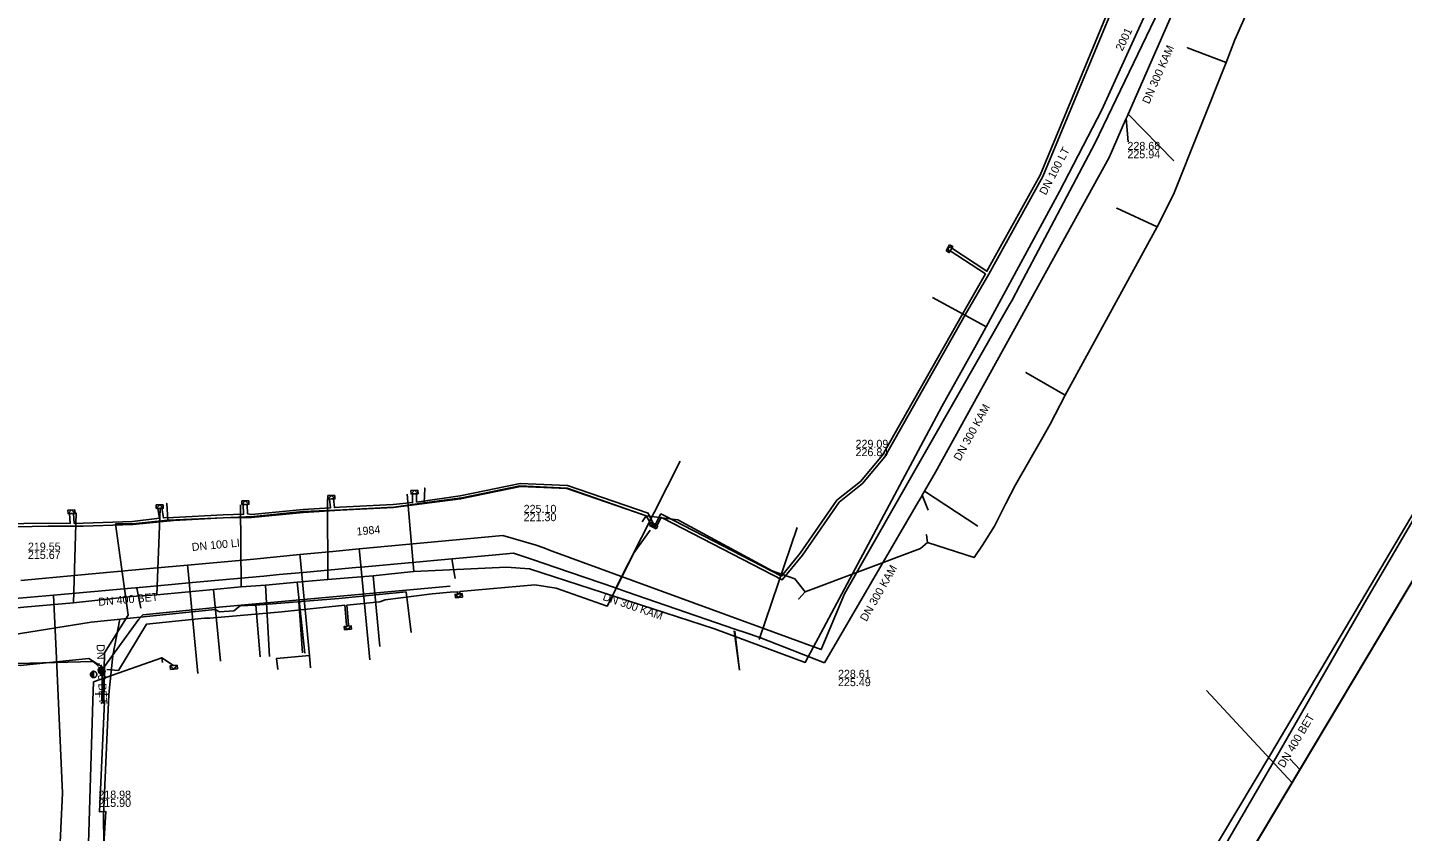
# Model space of a CAD drawing. Extents: x -596024 to -594475, y -1163820 to -1161957.
# Drawn here: x -595805.3 to -595667.9, y -1163008.8 to -1162928.4 of the extents above; entities that cross this region are included whole.
import ezdxf

# ---------------------------------------------------------------- set-up
doc = ezdxf.new("R2010")
doc.units = 0
for name, color, linetype in [('13', 7, 'Continuous'), ('31', 7, 'Continuous'), ('Level 1', 7, 'Continuous'), ('Vrstva 1', 7, 'Continuous'), ('Vrstva 12', 7, 'Continuous'), ('Vrstva 13', 7, 'Continuous'), ('Vrstva 15', 7, 'Continuous'), ('Vrstva 16', 7, 'Continuous'), ('Vrstva 25', 7, 'Continuous'), ('Vrstva 28', 7, 'Continuous'), ('Vrstva 4', 7, 'Continuous'), ('Vrstva 42', 7, 'Continuous'), ('Vrstva 43', 7, 'Continuous'), ('Vrstva 51', 7, 'Continuous'), ('Vrstva 55', 7, 'Continuous'), ('Vrstva 9', 7, 'Continuous')]:
    doc.layers.add(name, color=color, linetype=linetype)

# ---------------------------------------------------------------- blocks, each defined once
blk = doc.blocks.new('NN630')
at = {"layer": '31'}
for points in [[(-0.003, -0.7), (-0.703, 0)], [(-0.703, -0.7), (-0.703, 0), (0.697, 0), (0.697, -0.7)], [(-0.003, -0.7), (0.697, 0)], [(-0.703, -0.7), (0.697, -0.7)]]:
    blk.add_lwpolyline(points, dxfattribs=at)
blk = doc.blocks.new('NN510')
at = {"layer": '13'}
blk.add_lwpolyline([(0.001, 0.002), (0.001, 0.939)], dxfattribs=at)
blk = doc.blocks.new('NN440')
at = {"layer": '13'}
for points in [[(-0.631, 0), (0.629, 0)], [(0.631, -0.004), (0.627, 0.062), (0.617, 0.127), (0.6, 0.191), (0.577, 0.252), (0.547, 0.311), (0.511, 0.366), (0.469, 0.417), (0.423, 0.464), (0.371, 0.505), (0.316, 0.542), (0.257, 0.571), (0.196, 0.595), (0.132, 0.612), (0.067, 0.622), (0.001, 0.626), (-0.065, 0.622), (-0.13, 0.612), (-0.194, 0.595), (-0.255, 0.571), (-0.314, 0.542), (-0.369, 0.505), (-0.42, 0.464), (-0.467, 0.417), (-0.509, 0.366), (-0.544, 0.311), (-0.574, 0.252), (-0.598, 0.191), (-0.615, 0.127), (-0.626, 0.062), (-0.629, -0.004), (-0.626, -0.07), (-0.615, -0.135), (-0.598, -0.199), (-0.574, -0.26), (-0.544, -0.319), (-0.509, -0.374), (-0.467, -0.426), (-0.42, -0.472), (-0.369, -0.514), (-0.314, -0.55), (-0.255, -0.58), (-0.194, -0.603), (-0.13, -0.62), (-0.065, -0.631), (0.001, -0.634), (0.067, -0.631), (0.132, -0.62), (0.196, -0.603), (0.257, -0.58), (0.316, -0.55), (0.371, -0.514), (0.423, -0.472), (0.469, -0.426), (0.511, -0.374), (0.547, -0.319), (0.577, -0.26), (0.6, -0.199), (0.617, -0.135), (0.627, -0.07), (0.631, -0.004)], [(-0.601, -0.177), (0.57, -0.177)], [(-0.513, -0.325), (0.501, -0.325)], [(-0.375, -0.473), (0.353, -0.473)]]:
    blk.add_lwpolyline(points, dxfattribs=at)
blk = doc.blocks.new('NN620')
at = {"layer": 'Vrstva 28'}
for points in [[(0.752, 0.004), (-0.748, 0.004)], [(-0.748, 0.004), (-0.748, -0.746)], [(0.752, -0.746), (0.752, 0.004)], [(-0.748, -0.746), (0.752, -0.746)], [(0.368, -0.18), (-0.376, -0.18)], [(-0.376, -0.18), (-0.376, -0.558)], [(-0.376, -0.558), (0.368, -0.558)], [(0.321, -0.227), (-0.329, -0.227)], [(-0.329, -0.227), (-0.329, -0.51)], [(-0.329, -0.51), (0.321, -0.51)], [(0.274, -0.274), (-0.281, -0.274)], [(-0.281, -0.274), (-0.281, -0.463)], [(-0.281, -0.463), (0.274, -0.463)], [(0.227, -0.321), (-0.234, -0.321)], [(-0.234, -0.321), (-0.234, -0.416)], [(-0.234, -0.416), (0.227, -0.416)], [(-0.193, -0.369), (0.185, -0.369)], [(0.227, -0.416), (0.227, -0.321)], [(0.274, -0.463), (0.274, -0.274)], [(0.321, -0.51), (0.321, -0.227)], [(0.368, -0.558), (0.368, -0.18)]]:
    blk.add_lwpolyline(points, dxfattribs=at)

msp = doc.modelspace()

# ---------------------------------------------------------------- linework, layer by layer
at = {"layer": 'Level 1'}
for points in [[(-595609.54, -1162875.48), (-595633.36, -1162922.71), (-595657.34, -1162967.78), (-595683.27, -1163011.26), (-595711.29, -1163052.41), (-595741.62, -1163091.74), (-595776.38, -1163127.71), (-595816.28, -1163159.56), (-595860.78, -1163185.25), (-595904.58, -1163202.66), (-595939.49, -1163211.28), (-595963.53, -1163187.96), (-595972.46, -1163189.04), (-595993.41, -1163187.54), (-595999.33, -1163186.65), (-596024.42, -1163184.939)], [(-595695.46, -1162937.49), (-595695.26, -1162939.84)], [(-595695.28, -1162937.07), (-595690.7, -1162941.73)], [(-595740.04, -1162971.74), (-595746.52, -1162984.5)], [(-595715.28, -1162976.66), (-595715.86, -1162975.16)], [(-595710.31, -1162978.24), (-595715.62, -1162974.74)], [(-595732.15, -1162989.59), (-595728.36, -1162978.39)], [(-595762.55, -1162983.48), (-595762.87, -1162981.52)], [(-595793.95, -1162986.46), (-595794.35, -1162984.45)], [(-595734.12, -1162992.64), (-595734.66, -1162988.7)], [(-595734.12, -1162992.63), (-595734.6, -1162988.73)], [(-595687.46, -1162994.67), (-595678.89, -1163003.92)], [(-595679.1, -1163001.49), (-595678.1, -1163002.6)]]:
    msp.add_lwpolyline(points, dxfattribs=at)
at = {"layer": 'Vrstva 1'}
msp.add_line((-595657.36, -1162967.74), (-595683.3, -1163011.28), dxfattribs=at)
at = {"layer": 'Vrstva 13'}
for points in [[(-595691.75, -1162925.735), (-595698.61, -1162940), (-595706.11, -1162954.191), (-595706.88, -1162955.65), (-595707.17, -1162956.154), (-595723.63, -1162985.02), (-595725.95, -1162990.59), (-595752.837, -1162980.749), (-595753.78, -1162980.39), (-595754.435, -1162980.153)], [(-595805.955, -1162983.689), (-595800.236, -1162983.145), (-595792.699, -1162982.434), (-595789.273, -1162982.129), (-595782.644, -1162981.532), (-595778.049, -1162981.078), (-595774.777, -1162980.772), (-595772.121, -1162980.523), (-595765.671, -1162979.918), (-595757.763, -1162979.178), (-595754.435, -1162980.153)], [(-595772.121, -1162980.523), (-595772.098, -1162980.777), (-595771.082, -1162991.608)], [(-595789.273, -1162982.129), (-595789.246, -1162982.42), (-595788.256, -1162992.991)], [(-595778.049, -1162981.078), (-595778.023, -1162981.358), (-595777.104, -1162991.16), (-595776.988, -1162992.399)], [(-595777.104, -1162991.16), (-595780.382, -1162991.467), (-595780.253, -1162992.562)]]:
    msp.add_lwpolyline(points, dxfattribs=at)
at = {"layer": 'Vrstva 16'}
for points in [[(-595692.22, -1162924.07), (-595697.92, -1162936.64), (-595702.15, -1162944.8), (-595709.46, -1162958.31), (-595710.43, -1162960.09), (-595713.89, -1162966.27), (-595727.55, -1162991.87), (-595736.62, -1162988.52), (-595755.1, -1162982.52), (-595757.41, -1162982.34), (-595766.66, -1162982.77), (-595768.91, -1162983.01)], [(-595709.46, -1162958.31), (-595709.64, -1162958.22), (-595711.39, -1162957.26), (-595714.83, -1162955.4)], [(-595766.66, -1162982.77), (-595767.35, -1162975.04)], [(-595792.36, -1162985.1), (-595792.03, -1162976.51)], [(-595783.91, -1162984.32), (-595783.98, -1162976.13)], [(-595775.26, -1162983.57), (-595775.29, -1162975.54)], [(-595800.67, -1162985.9), (-595800.4, -1162976.92)], [(-595768.91, -1162983.01), (-595770.73, -1162983.2), (-595775.26, -1162983.57), (-595778.34, -1162983.85), (-595781.48, -1162984.13), (-595783.91, -1162984.32), (-595786.7, -1162984.59), (-595792.36, -1162985.1), (-595794.87, -1162985.27), (-595800.67, -1162985.9), (-595805.65, -1162986.36), (-595815.38, -1162987.29), (-595822.51, -1162987.94), (-595823.73, -1162988.13), (-595827.32, -1162988.38), (-595838.51, -1162989.4), (-595855.98, -1162991.08), (-595856.38, -1162991.12), (-595864.37, -1162991.89), (-595886.83, -1162993.96), (-595891.02, -1162994.31), (-595892.36, -1162994.43), (-595895.41, -1162994.94), (-595900.64, -1162995.37)], [(-595770.73, -1162983.2), (-595770.08, -1162990.27)], [(-595786.7, -1162984.59), (-595785.99, -1162991.74)], [(-595781.48, -1162984.13), (-595781.1, -1162991.27)], [(-595778.34, -1162983.85), (-595777.57, -1162990.93)]]:
    msp.add_lwpolyline(points, dxfattribs=at)
at = {"layer": 'Vrstva 25'}
for p, q in [((-595767.447, -1162984.818), (-595774.156, -1162985.488)), ((-595766.928, -1162988.866), (-595767.447, -1162984.818)), ((-595784.027, -1162986.2), (-595784.668, -1162986.72)), ((-595782.453, -1162986.153), (-595784.027, -1162986.2)), ((-595774.156, -1162985.488), (-595782.453, -1162986.153)), ((-595782.453, -1162986.153), (-595782.018, -1162991.314)), ((-595778.15, -1162985.808), (-595777.785, -1162990.913)), ((-595786.527, -1162986.568), (-595798.933, -1162987.835)), ((-595796.064, -1162987.542), (-595796.749, -1162991.185)), ((-595786.081, -1162986.809), (-595786.527, -1162986.568)), ((-595784.668, -1162986.72), (-595786.081, -1162986.809)), ((-595798.933, -1162987.835), (-595806.804, -1162989.096)), ((-595796.749, -1162991.185), (-595797.142, -1162995.061)), ((-595797.142, -1162995.061), (-595798.507, -1162995.013)), ((-595797.142, -1162995.061), (-595797.681, -1163007.177)), ((-595797.681, -1163007.177), (-595797.654, -1163009.979))]:
    msp.add_line(p, q, dxfattribs=at)
at = {"layer": 'Vrstva 42'}
for points in [[(-595742.344, -1162978.159), (-595741.965, -1162977.366), (-595741.785, -1162977.458), (-595729.841, -1162983.609), (-595727.83, -1162981.14), (-595724.169, -1162975.854), (-595721.815, -1162973.988), (-595719.596, -1162971.316), (-595711.55, -1162957.124), (-595709.209, -1162953.054), (-595703.795, -1162943.295), (-595696.888, -1162926.646), (-595697.024, -1162924.269), (-595698.97, -1162923.163), (-595698.88, -1162923.027), (-595698.784, -1162922.902), (-595696.975, -1162923.95), (-595694.006, -1162919.494), (-595692.928, -1162917.913), (-595688.388, -1162907.559), (-595687.875, -1162905.507), (-595690.849, -1162895.069), (-595691.201, -1162894.28), (-595691.24, -1162894.08)], [(-595742.522, -1162978.05), (-595741.969, -1162977.025), (-595741.647, -1162977.192), (-595729.919, -1162983.231), (-595728.07, -1162980.96), (-595724.391, -1162975.646), (-595722.025, -1162973.772), (-595719.844, -1162971.144), (-595711.81, -1162956.976), (-595709.541, -1162953.027), (-595713.068, -1162950.718), (-595712.979, -1162950.591), (-595712.89, -1162950.448), (-595709.393, -1162952.766), (-595704.065, -1162943.165), (-595697.192, -1162926.594)], [(-595743.144, -1162977.704), (-595743.442, -1162977.198), (-595751.376, -1162974.488), (-595756.016, -1162974.291), (-595761.991, -1162975.516), (-595768.703, -1162976.379), (-595774.043, -1162976.66), (-595777.717, -1162976.879), (-595782.883, -1162977.38), (-595785.729, -1162977.43), (-595790.668, -1162977.689), (-595794.751, -1162978.069), (-595799.709, -1162978.251), (-595803.228, -1162978.24), (-595809.609, -1162978.365)], [(-595742.786, -1162977.907), (-595743.24, -1162976.95), (-595751.32, -1162974.19), (-595756.04, -1162973.99), (-595762.04, -1162975.22), (-595766.39, -1162975.841), (-595766.4, -1162975.008), (-595766.6, -1162975.01), (-595766.8, -1162975.012), (-595766.79, -1162975.883), (-595768.73, -1162976.08), (-595774.06, -1162976.36), (-595774.6, -1162976.387), (-595774.701, -1162975.507), (-595774.9, -1162975.53), (-595775.099, -1162975.553), (-595775, -1162976.415), (-595777.74, -1162976.58), (-595782.9, -1162977.08), (-595783.29, -1162977.025), (-595783.31, -1162976.066), (-595783.51, -1162976.07), (-595783.71, -1162976.074), (-595783.69, -1162977.049), (-595785.74, -1162977.13), (-595790.69, -1162977.39), (-595791.699, -1162977.421), (-595791.863, -1162976.427), (-595792.06, -1162976.46), (-595792.257, -1162976.493), (-595792.1, -1162977.442), (-595794.77, -1162977.77), (-595799.714, -1162977.951), (-595800.61, -1162977.968), (-595800.68, -1162976.966), (-595800.88, -1162976.98), (-595801.08, -1162976.994), (-595801.011, -1162977.977), (-595803.23, -1162977.94), (-595808.11, -1162978.03)], [(-595797.366, -1162992.591), (-595796.19, -1162992.69), (-595793.39, -1162988.06), (-595787.58, -1162987.43), (-595787.05, -1162987.45), (-595779.86, -1162986.8), (-595773.56, -1162986.15), (-595773.393, -1162988.102), (-595773.28, -1162988.24), (-595773.191, -1162988.102), (-595773.36, -1162986.131), (-595770.07, -1162985.82), (-595769.52, -1162985.6), (-595764.84, -1162985.02), (-595763.03, -1162984.85), (-595762.261, -1162984.797), (-595762.292, -1162984.971), (-595762.2, -1162985.03), (-595762.083, -1162984.941), (-595762.057, -1162984.781), (-595754.58, -1162984.1), (-595752.45, -1162984.45), (-595747.35, -1162986.26), (-595744.64, -1162980.89), (-595743.04, -1162978.635)], [(-595807.57, -1162992.01), (-595798.72, -1162991.77), (-595798.261, -1162992.136)]]:
    msp.add_lwpolyline(points, dxfattribs=at)
at = {"layer": 'Vrstva 51'}
for points in [[(-595798.693, -1162993.822), (-595791.859, -1162991.405), (-595790.683, -1162992.186)], [(-595798.693, -1162993.822), (-595798.752, -1162995.701), (-595799.6, -1163023.09), (-595799.91, -1163059.77)]]:
    msp.add_lwpolyline(points, dxfattribs=at)
at = {"layer": 'Vrstva 55'}
for points in [[(-595861.545, -1163184.149), (-595840.235, -1163173.489), (-595821.055, -1163161.559), (-595807.835, -1163152.609), (-595783.535, -1163132.569), (-595767.875, -1163118.239), (-595756.215, -1163105.649), (-595737.945, -1163084.859), (-595715.895, -1163056.189), (-595701.725, -1163036.029), (-595690.385, -1163018.389), (-595680.305, -1163001.079), (-595671.485, -1162985.639), (-595658.565, -1162963.599), (-595646.285, -1162940.289), (-595632.685, -1162914.289), (-595612.515, -1162873.319), (-595603.855, -1162853.619), (-595604.51, -1162853.03)], [(-595904.003, -1163200.83), (-595885.89, -1163194.12), (-595862.2, -1163183.56), (-595840.89, -1163172.9), (-595821.71, -1163160.97), (-595808.49, -1163152.02), (-595784.19, -1163131.98), (-595768.53, -1163117.65), (-595756.87, -1163105.06), (-595738.6, -1163084.27), (-595716.55, -1163055.6), (-595702.38, -1163035.44), (-595691.04, -1163017.8), (-595681.06, -1163001.07), (-595661.01, -1162967.24), (-595642.49, -1162932.63), (-595625.54, -1162899.15), (-595608.632, -1162864.051)], [(-595743.84, -1162977.81), (-595743.46, -1162977.21), (-595740.29, -1162977.62), (-595730.87, -1162982.7), (-595728.58, -1162983.51), (-595727.55, -1162984.82), (-595728.2, -1162985.52), (-595727.55, -1162984.82), (-595716.03, -1162980.47), (-595715.32, -1162979.87), (-595715.43, -1162979.11), (-595715.32, -1162979.87), (-595710.65, -1162981.39), (-595709.82, -1162980.14), (-595708.62, -1162978.26), (-595707.5, -1162975.98), (-595706.53, -1162974.11), (-595703.94, -1162969.59), (-595703.07, -1162968.04), (-595701.58, -1162965.15), (-595705.49, -1162962.87), (-595701.58, -1162965.15), (-595692.39, -1162948.31), (-595696.41, -1162946.46), (-595692.39, -1162948.31), (-595690.75, -1162945.1), (-595685.49, -1162931.9), (-595689.35, -1162930.43), (-595685.49, -1162931.9), (-595684.6, -1162929.63), (-595678.1, -1162914.84)], [(-595797.58, -1162995.79), (-595797.67, -1162995.95), (-595797.57, -1162990.9), (-595795.23, -1162987.15), (-595796.48, -1162978.03), (-595794.8, -1162978.03), (-595791.27, -1162977.65), (-595791.37, -1162975.97), (-595791.27, -1162977.65), (-595785.72, -1162977.43), (-595782.68, -1162977.27), (-595777.74, -1162976.78), (-595773.77, -1162976.62), (-595768.67, -1162976.35), (-595765.63, -1162975.91), (-595765.57, -1162974.44), (-595765.63, -1162975.91), (-595761.88, -1162975.42), (-595756.07, -1162974.23), (-595751.34, -1162974.44), (-595743.46, -1162977.21), (-595743.84, -1162977.81)], [(-595797.935, -1162995.99), (-595797.641, -1162995.725), (-595797.577, -1162992.268), (-595794.16, -1162987.53), (-595793.75, -1162987.1), (-595786.13, -1162986.33), (-595763.05, -1162984.25)], [(-595939.819, -1163011.071), (-595940.502, -1163004.494), (-595940.962, -1163003.452), (-595941.718, -1163002.328), (-595941.65, -1163002.05), (-595933.08, -1163001.23), (-595932.07, -1163000.53), (-595930.62, -1163000.08), (-595928.42, -1162999.84), (-595907.67, -1162997.81), (-595879.11, -1162994.94), (-595854.57, -1162992.8), (-595830.89, -1162990.61), (-595812.28, -1162988.92), (-595811.32, -1162989.67), (-595808.88, -1162991.91), (-595806.03, -1162992.18), (-595799.16, -1162991.49), (-595797.779, -1162992.349), (-595797.839, -1162995.635), (-595797.925, -1162995.712)], [(-595797.58, -1162995.79), (-595798.1, -1163006.79), (-595797.46, -1163006.77), (-595798.03, -1163016.07)]]:
    msp.add_lwpolyline(points, dxfattribs=at)
at = {"layer": 'Vrstva 9'}
for points in [[(-595697.17, -1162941.38), (-595695.529, -1162937.64), (-595695.462, -1162937.488), (-595695.344, -1162937.219), (-595695.277, -1162937.067), (-595690.133, -1162925.349), (-595690.132, -1162925.347), (-595687.556, -1162919.478), (-595687.407, -1162919.138), (-595679.788, -1162901.783), (-595679.19, -1162900.42)], [(-595714.54, -1162972.85), (-595706.61, -1162958.483), (-595697.17, -1162941.38)], [(-595714.54, -1162972.85), (-595715.619, -1162974.741), (-595715.857, -1162975.158), (-595716.001, -1162975.405), (-595716.217, -1162975.776), (-595725.619, -1162991.918)], [(-595756.692, -1162980.948), (-595758.465, -1162981.11), (-595771.56, -1162982.307), (-595772.466, -1162982.39), (-595777.714, -1162982.87), (-595780.134, -1162983.091), (-595781.658, -1162983.23), (-595782.056, -1162983.267), (-595789.167, -1162983.917), (-595790.84, -1162984.07), (-595794.494, -1162984.404), (-595794.903, -1162984.441), (-595797.492, -1162984.678), (-595802.67, -1162985.151)], [(-595725.619, -1162991.918), (-595731.151, -1162989.754), (-595732.08, -1162989.39), (-595733.557, -1162988.881), (-595734.482, -1162988.563), (-595745.424, -1162984.797), (-595746.5, -1162984.427), (-595752.487, -1162982.367), (-595753.631, -1162981.973), (-595754.698, -1162981.606), (-595756.692, -1162980.948)], [(-595802.67, -1162985.151), (-595805.752, -1162985.399), (-595816.885, -1162986.296), (-595824.84, -1162986.937), (-595829.136, -1162987.283), (-595831.07, -1162987.439), (-595833.093, -1162987.602), (-595834.927, -1162987.75)], [(-595801.773, -1163004.934), (-595802.418, -1162990.709), (-595802.67, -1162985.151)], [(-595801.773, -1163004.934), (-595802.109, -1163011.966), (-595802.214, -1163014.162), (-595802.28, -1163015.552), (-595802.371, -1163017.451), (-595802.503, -1163020.231), (-595802.54, -1163021)]]:
    msp.add_lwpolyline(points, dxfattribs=at)

# ---------------------------------------------------------------- block references
at = {"layer": 'Vrstva 43'}
for name, p, xscale, yscale, rotation in [('NN630', (-595712.979, -1162950.591), 0.5, 0.5, -119), ('NN630', (-595774.9, -1162975.53), 0.5, 0.5, -179.00000000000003), ('NN630', (-595766.6, -1162975.01), 0.5, 0.5, -179.00000000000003), ('NN630', (-595800.88, -1162976.98), 0.5, 0.5, -179.00000000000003), ('NN630', (-595792.06, -1162976.46), 0.5, 0.5, -179.00000000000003), ('NN630', (-595783.51, -1162976.07), 0.5, 0.5, -179.00000000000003), ('NN620', (-595742.61, -1162978.02), 0.49999999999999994, 0.5000000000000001, -28.99999999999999), ('NN630', (-595762.199, -1162985.029), 0.5, 0.5000000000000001, 6), ('NN630', (-595773.28, -1162988.24), 0.5, 0.5000000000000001, 6), ('NN510', (-595791.859, -1162991.405), 0.5, 0.49999999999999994, -173.00000000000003), ('NN440', (-595798.671, -1162993.07), 0.5, 0.5, -90.00000000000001), ('NN620', (-595798.061, -1162992.884), 0.5, 0.5, 119.99999999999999), ('NN630', (-595790.683, -1162992.187), 0.5, 0.5000000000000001, 6)]:
    msp.add_blockref(name, p, dxfattribs=dict(at, xscale=xscale, yscale=yscale, rotation=rotation))

# ---------------------------------------------------------------- texts
at = {"layer": 'Vrstva 12'}
for s, rotation, p in [('DN 300 KAM', 66.29122, (-595693.176, -1162936.106)), ('DN 300 KAM', 61.0773, (-595712.073, -1162971.791)), ('DN 300 KAM', 60.27516, (-595721.433, -1162987.842)), ('DN 400 BET', 5.0019, (-595798.173, -1162986.221)), ('DN 300 KAM', 341.02448, (-595747.851, -1162985.61)), ('DN 300 BET', 272.59612, (-595798.378, -1162990.058))]:
    msp.add_text(s, height=0.8, rotation=rotation, dxfattribs=at).set_placement(p)
for s, p in [('228.68', (-595695.347, -1162940.634)), ('225.94', (-595695.347, -1162941.466)), ('229.09', (-595722.521, -1162970.413)), ('226.84', (-595722.521, -1162971.245)), ('225.10', (-595755.692, -1162976.916)), ('221.30', (-595755.692, -1162977.748)), ('219.55', (-595805.24, -1162980.689)), ('215.67', (-595805.24, -1162981.521)), ('228.61', (-595724.276, -1162993.408)), ('225.49', (-595724.276, -1162994.24)), ('218.98', (-595798.203, -1163005.482)), ('215.90', (-595798.203, -1163006.314))]:
    msp.add_text(s, height=0.8, dxfattribs=at).set_placement(p)
at = {"layer": 'Vrstva 15'}
for s, rotation, p in [('2001', 64.34316, (-595695.856, -1162930.818)), ('DN 100 LT', 62.16592, (-595703.503, -1162945.214)), ('1984', 5.32851, (-595772.356, -1162979.183)), ('DN 100 LI', 5.32851, (-595788.829, -1162980.733))]:
    msp.add_text(s, height=0.8, rotation=rotation, dxfattribs=at).set_placement(p)
at = {"layer": 'Vrstva 4'}
msp.add_text('DN 400 BET', height=0.8, rotation=59.18654, dxfattribs=at).set_placement((-595679.699, -1163002.467))

doc.saveas('drawing.dxf')
